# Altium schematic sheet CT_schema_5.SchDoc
size 522 x 390 mm
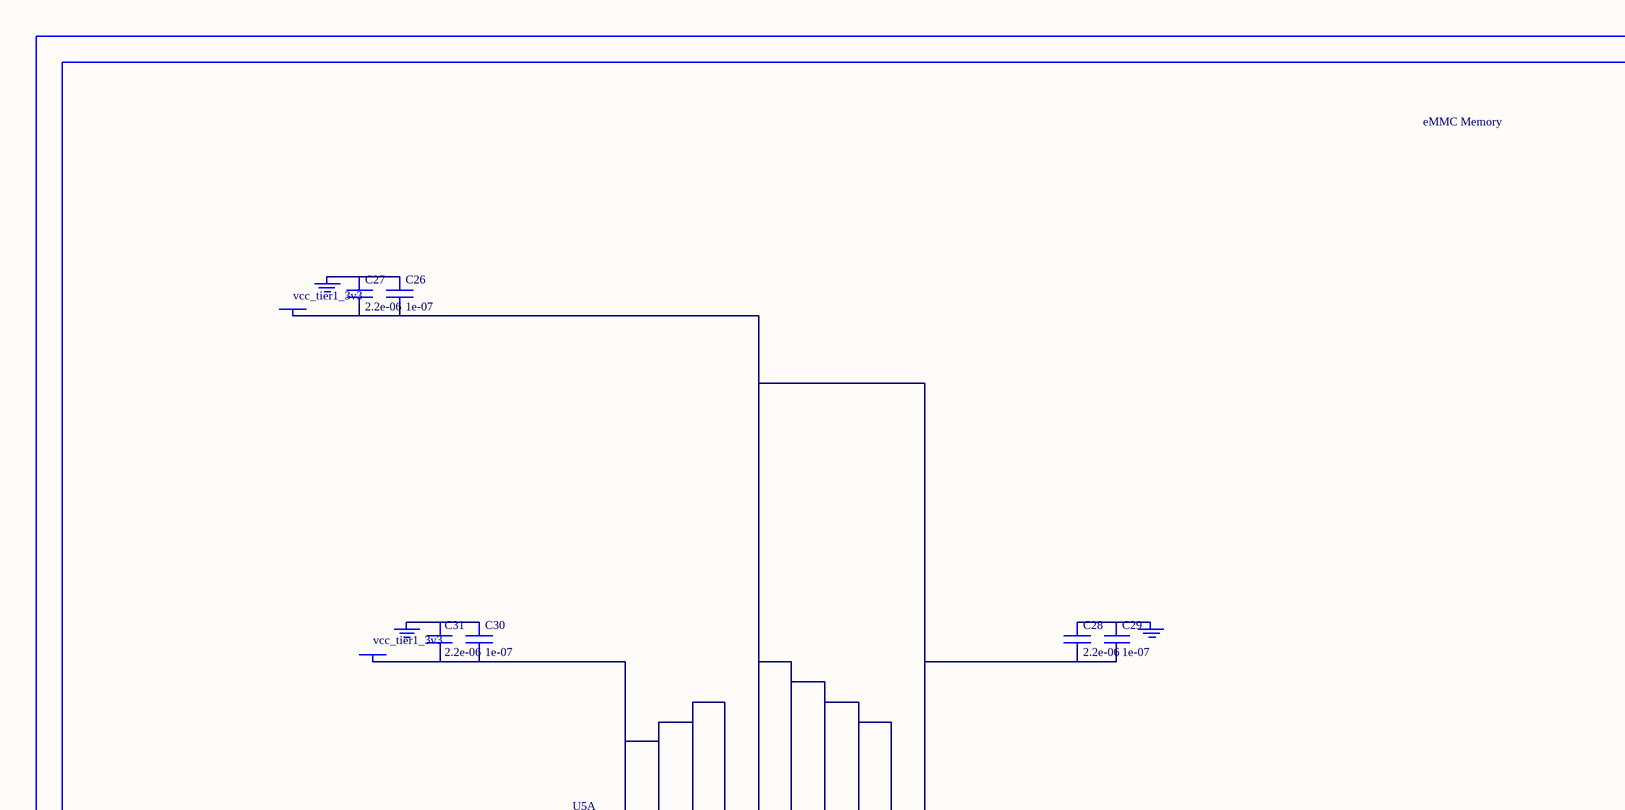
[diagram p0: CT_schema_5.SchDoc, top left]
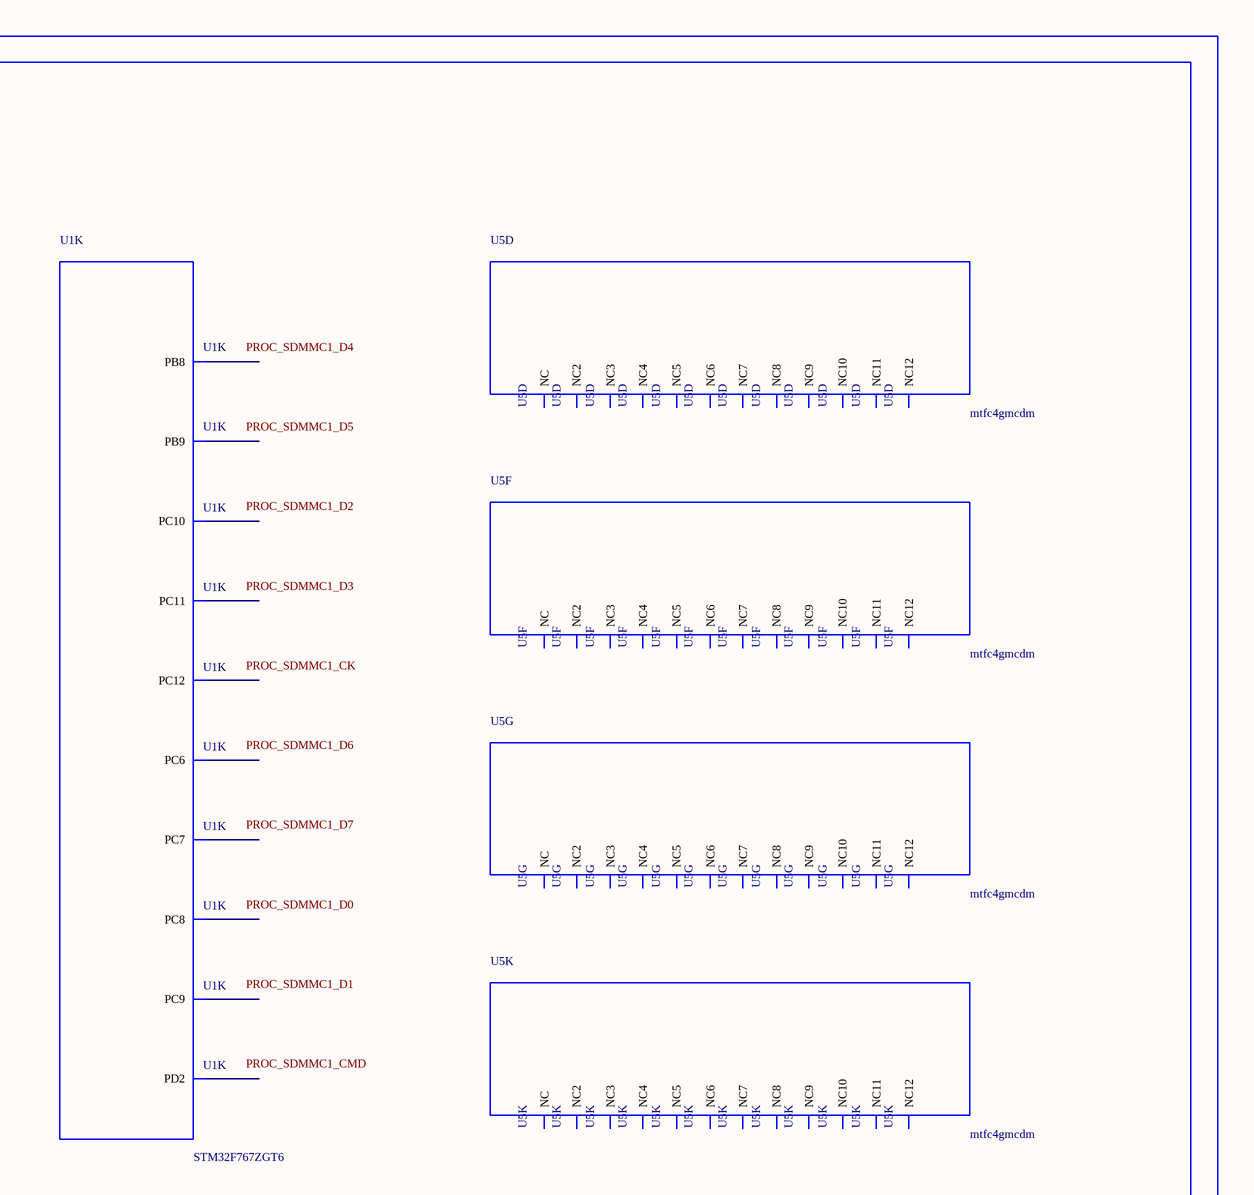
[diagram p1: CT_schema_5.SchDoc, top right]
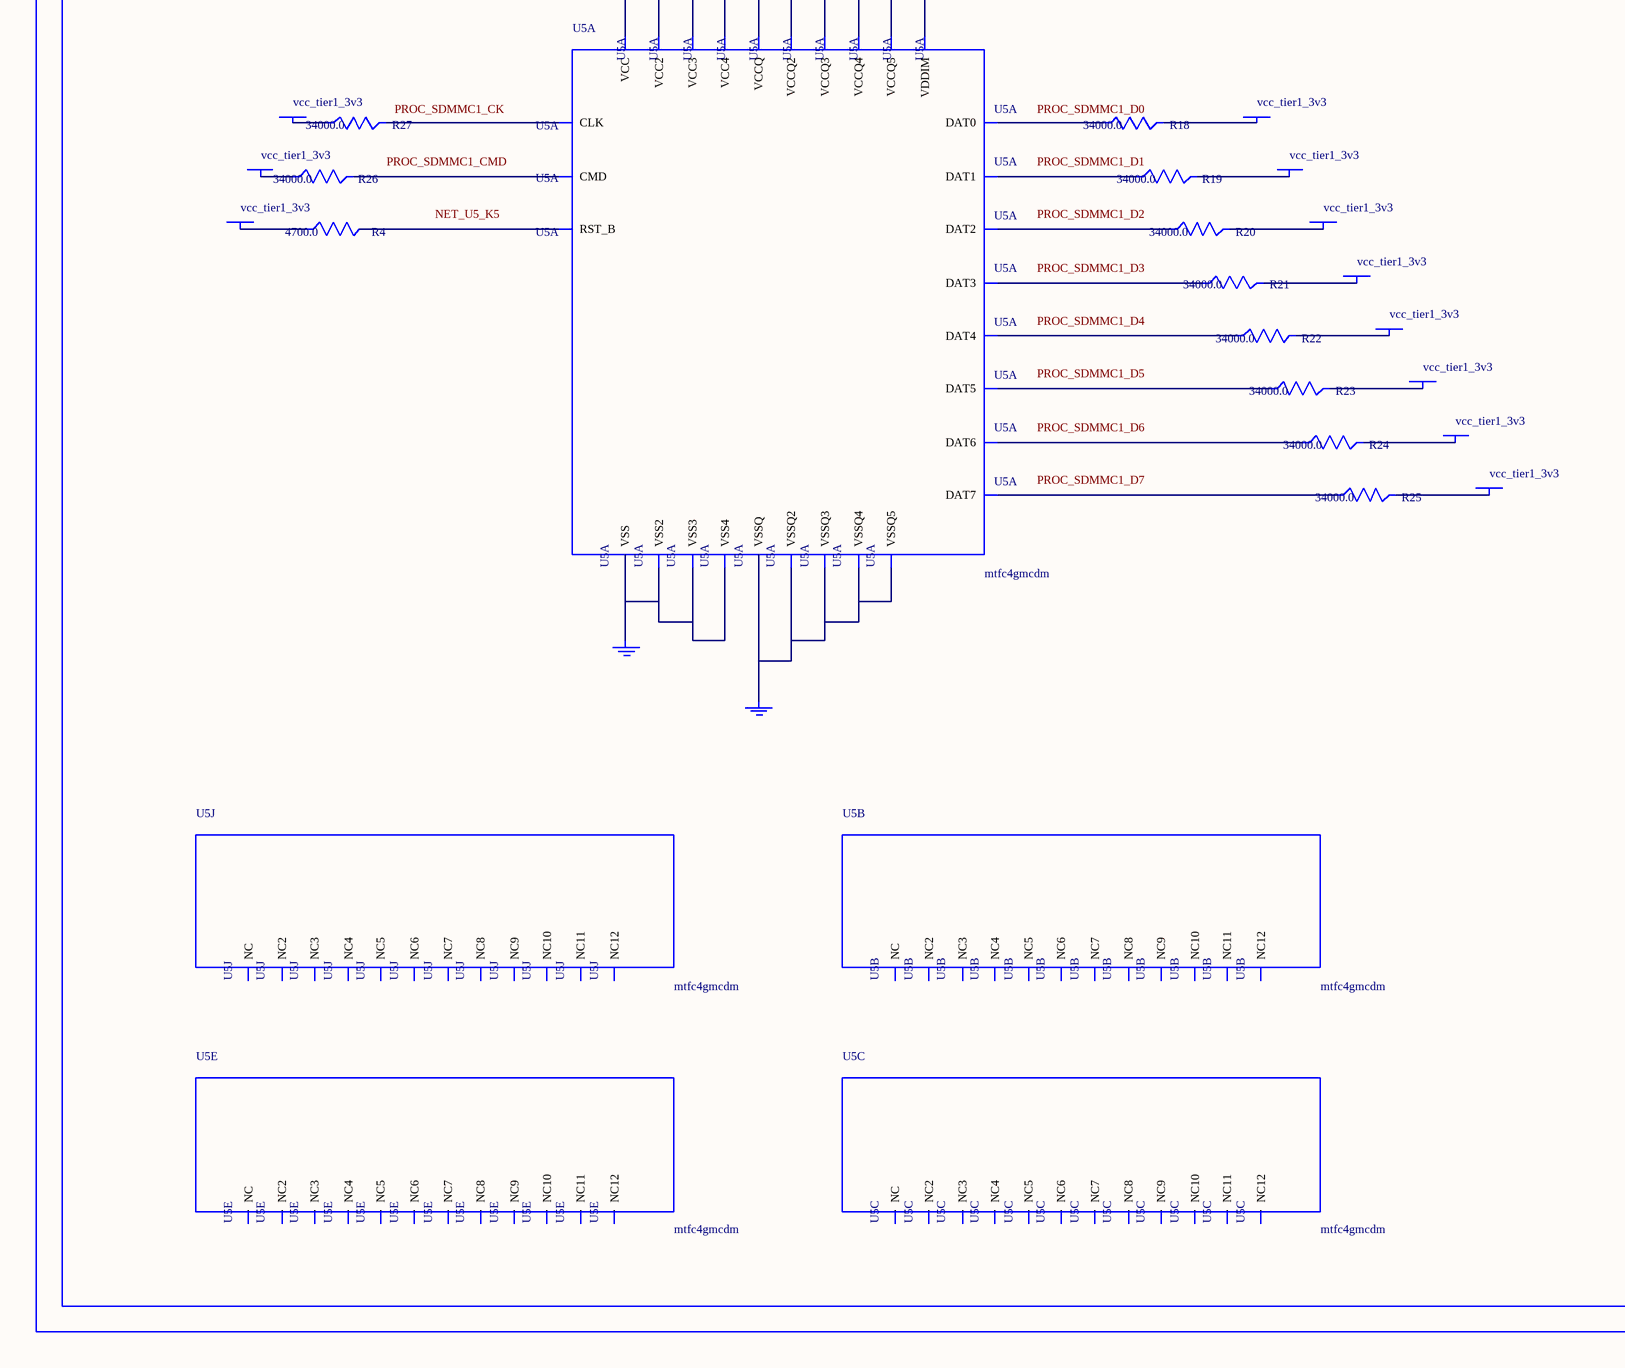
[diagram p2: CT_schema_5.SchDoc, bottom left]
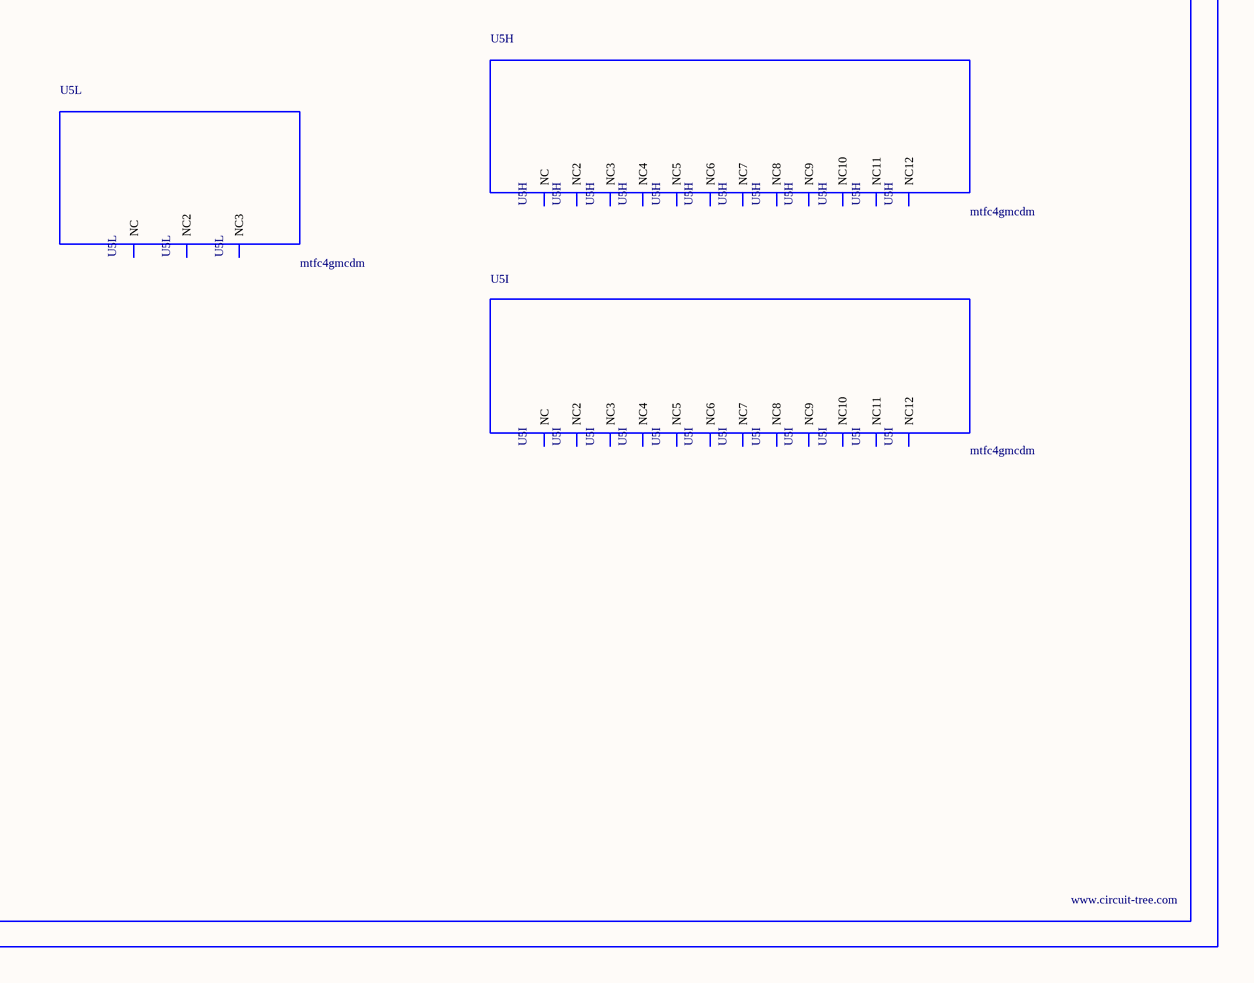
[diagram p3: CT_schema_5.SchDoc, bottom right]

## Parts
BORDER4  (no value)
C26  1e-07  [C0402]
C27  2.2e-06  [C0603]
C28  2.2e-06  [C0603]
C29  1e-07  [C0402]
C30  1e-07  [C0402]
C31  2.2e-06  [C0603]
GND_INSTANCE_4_0  (no value)
GND_INSTANCE_4_1  (no value)
GND_INSTANCE_4_2  (no value)
GND_INSTANCE_4_3  (no value)
GND_INSTANCE_4_4  (no value)
POWER_INSTANCE_4_0  vcc_tier1_3v3
POWER_INSTANCE_4_1  vcc_tier1_3v3
POWER_INSTANCE_4_2  vcc_tier1_3v3
POWER_INSTANCE_4_3  vcc_tier1_3v3
POWER_INSTANCE_4_4  vcc_tier1_3v3
POWER_INSTANCE_4_5  vcc_tier1_3v3
POWER_INSTANCE_4_6  vcc_tier1_3v3
POWER_INSTANCE_4_7  vcc_tier1_3v3
POWER_INSTANCE_4_8  vcc_tier1_3v3
POWER_INSTANCE_4_9  vcc_tier1_3v3
POWER_INSTANCE_4_10  vcc_tier1_3v3
POWER_INSTANCE_4_11  vcc_tier1_3v3
POWER_INSTANCE_4_12  vcc_tier1_3v3
R4  4700.0  [R0603]
R18  34000.0  [R0603]
R19  34000.0  [R0603]
R20  34000.0  [R0603]
R21  34000.0  [R0603]
R22  34000.0  [R0603]
R23  34000.0  [R0603]
R24  34000.0  [R0603]
R25  34000.0  [R0603]
R26  34000.0  [R0603]
R27  34000.0  [R0603]
U1  STM32F767ZGT6  [LQFP144]  (part K of 13)
U5  mtfc4gmcdm  [TFBGA-153]  (parts A,B,C,D,E,F,G,H,I,J,K,L of 12)

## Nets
NetC26_1: C26.1 C27.1 GND_INSTANCE_4_0.0(GND)
NetC26_2: C26.2 C27.2 C28.2 C29.2 POWER_INSTANCE_4_0.0(PWR) U5.C2(VDDIM) U5.C6(VCCQ) U5.M4(VCCQ2) U5.N4(VCCQ3) U5.P3(VCCQ4) U5.P5(VCCQ5)
NetC28_1: C28.1 C29.1 GND_INSTANCE_4_1.0(GND)
NetC30_1: C30.1 C31.1 GND_INSTANCE_4_2.0(GND)
NetC30_2: C30.2 C31.2 POWER_INSTANCE_4_1.0(PWR) U5.E6(VCC) U5.F5(VCC2) U5.J10(VCC3) U5.K9(VCC4)
NetGND_INSTANCE_4_3_0: GND_INSTANCE_4_3.0(GND) U5.E7(VSS) U5.G5(VSS2) U5.H10(VSS3) U5.K8(VSS4)
NetGND_INSTANCE_4_4_0: GND_INSTANCE_4_4.0(GND) U5.C4(VSSQ) U5.N2(VSSQ2) U5.N5(VSSQ3) U5.P4(VSSQ4) U5.P6(VSSQ5)
NetPOWER_INSTANCE_4_2_0: POWER_INSTANCE_4_2.0(PWR) R18.2
NetPOWER_INSTANCE_4_3_0: POWER_INSTANCE_4_3.0(PWR) R19.2
NetPOWER_INSTANCE_4_4_0: POWER_INSTANCE_4_4.0(PWR) R20.2
NetPOWER_INSTANCE_4_5_0: POWER_INSTANCE_4_5.0(PWR) R21.2
NetPOWER_INSTANCE_4_6_0: POWER_INSTANCE_4_6.0(PWR) R22.2
NetPOWER_INSTANCE_4_7_0: POWER_INSTANCE_4_7.0(PWR) R23.2
NetPOWER_INSTANCE_4_8_0: POWER_INSTANCE_4_8.0(PWR) R24.2
NetPOWER_INSTANCE_4_9_0: POWER_INSTANCE_4_9.0(PWR) R25.2
NetPOWER_INSTANCE_4_10_0: POWER_INSTANCE_4_10.0(PWR) R26.1
NetPOWER_INSTANCE_4_11_0: POWER_INSTANCE_4_11.0(PWR) R27.1
NetPOWER_INSTANCE_4_12_0: POWER_INSTANCE_4_12.0(PWR) R4.1
NetR4_2: R4.2 U5.K5(RST_B)
NetR18_1: R18.1 U5.A3(DAT0)
NetR19_1: R19.1 U5.A4(DAT1)
NetR20_1: R20.1 U5.A5(DAT2)
NetR21_1: R21.1 U5.B2(DAT3)
NetR22_1: R22.1 U5.B3(DAT4)
NetR23_1: R23.1 U5.B4(DAT5)
NetR24_1: R24.1 U5.B5(DAT6)
NetR25_1: R25.1 U5.B6(DAT7)
NetR26_2: R26.2 U5.M5(CMD)
NetR27_2: R27.2 U5.M6(CLK)

Not connected (* = marked no-connect by the designer): U1 96(PC6) 97(PC7) 98(PC8) 99(PC9) 111(PC10) 112(PC11) 113(PC12) 116(PD2) 139(PB8) 140(PB9); U5 A1(NC) A2(NC7) A6(NC8) A7(NC9) A8(NC10) A9(NC11) A10(NC2) A11(NC3) A12(NC4) A13(NC5) A14(NC6) B1(NC12) B7(NC6) B8(NC7) B9(NC8) B10(NC) B11(NC2) B12(NC3) B13(NC4) B14(NC5) C1(NC9) C3(NC10) C5(NC11) C7(NC12) C8(NC6) C9(NC7) C10(NC) C11(NC2) C12(NC3) C13(NC4) C14(NC5) D1(NC8) D2(NC10) D3(NC11) D4(NC12) D12(NC9) D13(NC) D14(NC2) E1(NC3) E2(NC8) E3(NC9) E5(NC10) E8(NC11) E9(NC12) E10(NC4) E12(NC5) E13(NC6) E14(NC7) F1(NC) F2(NC6) F3(NC7) F10(NC2) F12(NC3) F13(NC4) F14(NC5) G1(NC8) G2(NC11) G3(NC12) G10(NC9) G12(NC10) G13(NC) G14(NC2) H1(NC3) H2(NC7) H3(NC8) H5(NC9) H12(NC4) H13(NC5) H14(NC6) J1(NC10) J2(NC11) J3(NC12) J5(NC4) J12(NC) J13(NC2) J14(NC3) K1(NC5) K2(NC9) K3(NC10) K6(NC11) K7(NC12) K10(NC6) K12(NC7) K13(NC8) K14(NC) L1(NC2) L2(NC6) L3(NC7) L12(NC3) L13(NC4) L14(NC5) M1(NC8) M2(NC9) M3(NC10) M7(NC11) M8(NC12) M9(NC6) M10(NC) M11(NC2) M12(NC3) M13(NC4) M14(NC5) N1(NC7) N3(NC8) N6(NC9) N7(NC10) N8(NC11) N9(NC12) N10(NC) N11(NC2) N12(NC3) N13(NC4) N14(NC5) P1(NC6) P2(NC9) P7(NC10) P8(NC11) P9(NC12) P10(NC7) P11(NC8) P12(NC) P13(NC2) P14(NC3)

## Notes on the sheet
- Labels drawn without touching a wire or pin: NET_U5_K5, PROC_SDMMC1_CK, PROC_SDMMC1_CMD, PROC_SDMMC1_D0, PROC_SDMMC1_D1, PROC_SDMMC1_D2, PROC_SDMMC1_D3, PROC_SDMMC1_D4, PROC_SDMMC1_D5, PROC_SDMMC1_D6, PROC_SDMMC1_D7

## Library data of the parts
BORDER4 = BORDER_PAGE4
C26 C29 C30 = C0402C104K3RACTU
C27 C28 C31 = C0603C225K8RACTU
GND_INSTANCE_4_0-GND_INSTANCE_4_4 = GND
POWER_INSTANCE_4_0-POWER_INSTANCE_4_12 = PWR
R4 = RC0603JR-074K7L
R18-R27 = ERA3ARB3402V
